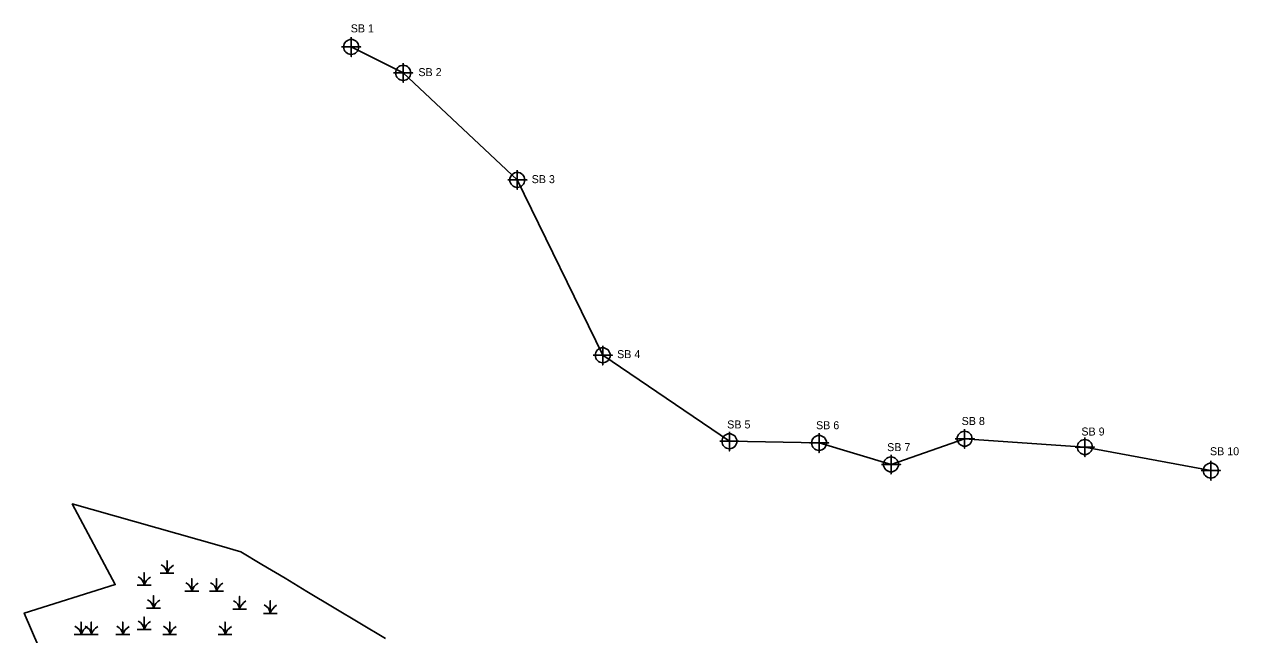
# Model space of a CAD drawing. Extents: x 2058476 to 2058911, y 688598 to 689103.
# Drawn here: x 2058475.6 to 2058854.9, y 688912 to 689102.8 of the extents above; entities that cross this region are included whole.
import ezdxf

# ---------------------------------------------------------------- set-up
doc = ezdxf.new("R2010")
doc.units = 0
for name, color, linetype in [('Exist Environmental Wetland Boundary', 7, 'Continuous'), ('Exist Hydro Jurisdictional Stream or Body of Water NEU Mitigable', 7, 'Continuous'), ('Exist Hydro Jurisdictional Stream or Body of Water NEU Mitigable Cogo Comment', 7, 'Continuous'), ('Exist Hydro Jurisdictional Stream or Body of Water NEU Mitigable Cogo Point CELL', 7, 'Continuous'), ('Exist Hydro Swamp or Marsh', 7, 'Continuous')]:
    doc.layers.add(name, color=color, linetype=linetype)

msp = doc.modelspace()

# ---------------------------------------------------------------- linework, layer by layer
at = {"layer": 'Exist Environmental Wetland Boundary'}
msp.add_lwpolyline([(2058588.45, 688910.87), (2058580.43, 688915.67), (2058572.43, 688920.46), (2058563.9, 688925.57), (2058557.1, 688929.64), (2058549.83, 688934), (2058543.26, 688937.93), (2058543.26, 688937.93), (2058536.49, 688939.85), (2058490.58, 688952.88), (2058504.01, 688927.66), (2058475.61, 688918.78), (2058492.26, 688880.08)], dxfattribs=at)
at = {"layer": 'Exist Hydro Jurisdictional Stream or Body of Water NEU Mitigable'}
msp.add_lwpolyline([(2058577.72, 689095.69), (2058593.95, 689087.58), (2058629.6, 689054.14), (2058656.28, 688999.33), (2058695.83, 688972.46), (2058723.84, 688971.95), (2058746.31, 688965.24), (2058769.31, 688973.26), (2058806.85, 688970.66), (2058846.21, 688963.3)], dxfattribs=at)
at = {"layer": 'Exist Hydro Jurisdictional Stream or Body of Water NEU Mitigable Cogo Point CELL'}
for points in [[(2058577.72, 689098.69), (2058577.72, 689092.69), (2058577.72, 689095.69), (2058580.72, 689095.69), (2058574.72, 689095.69)], [(2058593.95, 689090.58), (2058593.95, 689084.58), (2058593.95, 689087.58), (2058596.95, 689087.58), (2058590.95, 689087.58)], [(2058629.6, 689057.14), (2058629.6, 689051.14), (2058629.6, 689054.14), (2058632.6, 689054.14), (2058626.6, 689054.14)], [(2058656.28, 689002.33), (2058656.28, 688996.33), (2058656.28, 688999.33), (2058659.28, 688999.33), (2058653.28, 688999.33)], [(2058769.31, 688976.26), (2058769.31, 688970.26), (2058769.31, 688973.26), (2058772.31, 688973.26), (2058766.31, 688973.26)], [(2058695.83, 688975.46), (2058695.83, 688969.46), (2058695.83, 688972.46), (2058698.83, 688972.46), (2058692.83, 688972.46)], [(2058723.84, 688974.95), (2058723.84, 688968.95), (2058723.84, 688971.95), (2058726.84, 688971.95), (2058720.84, 688971.95)], [(2058806.85, 688973.66), (2058806.85, 688967.66), (2058806.85, 688970.66), (2058809.85, 688970.66), (2058803.85, 688970.66)], [(2058746.31, 688968.24), (2058746.31, 688962.24), (2058746.31, 688965.24), (2058749.31, 688965.24), (2058743.31, 688965.24)], [(2058846.21, 688966.3), (2058846.21, 688960.3), (2058846.21, 688963.3), (2058849.21, 688963.3), (2058843.21, 688963.3)]]:
    msp.add_lwpolyline(points, dxfattribs=at)
for centre in [(2058577.72, 689095.69), (2058593.95, 689087.58), (2058629.6, 689054.14), (2058656.28, 688999.33), (2058695.83, 688972.46), (2058723.84, 688971.95), (2058769.31, 688973.26), (2058806.85, 688970.66), (2058746.31, 688965.24), (2058846.21, 688963.3)]:
    msp.add_circle(centre, 2.34, dxfattribs=at)
at = {"layer": 'Exist Hydro Swamp or Marsh'}
msp.add_line((2058515.96, 688922.07), (2058515.96, 688922.07), dxfattribs=at)
for points in [[(2058518.07, 688931.21), (2058520.22, 688931.21), (2058520.22, 688935.15), (2058520.22, 688931.21), (2058522.37, 688931.21)], [(2058510.89, 688927.48), (2058513.04, 688927.48), (2058513.04, 688931.43), (2058513.04, 688927.48), (2058515.19, 688927.48)], [(2058525.79, 688925.62), (2058527.94, 688925.62), (2058527.94, 688929.56), (2058527.94, 688925.62), (2058530.09, 688925.62)], [(2058533.51, 688925.62), (2058535.66, 688925.62), (2058535.66, 688929.56), (2058535.66, 688925.62), (2058537.81, 688925.62)], [(2058513.81, 688920.29), (2058515.96, 688920.29), (2058515.96, 688924.24), (2058515.96, 688920.29), (2058518.12, 688920.29)], [(2058540.7, 688920.02), (2058542.85, 688920.02), (2058542.85, 688923.97), (2058542.85, 688920.02), (2058545, 688920.02)], [(2058550.28, 688918.69), (2058552.43, 688918.69), (2058552.43, 688922.64), (2058552.43, 688918.69), (2058554.58, 688918.69)], [(2058491.19, 688912.04), (2058493.34, 688912.04), (2058493.34, 688915.98), (2058493.34, 688912.04), (2058495.49, 688912.04)], [(2058494.38, 688912.04), (2058496.53, 688912.04), (2058496.53, 688915.98), (2058496.53, 688912.04), (2058498.69, 688912.04)], [(2058504.23, 688912.04), (2058506.38, 688912.04), (2058506.38, 688915.98), (2058506.38, 688912.04), (2058508.53, 688912.04)], [(2058510.89, 688913.63), (2058513.04, 688913.63), (2058513.04, 688917.58), (2058513.04, 688913.63), (2058515.19, 688913.63)], [(2058518.87, 688912.04), (2058521.02, 688912.04), (2058521.02, 688915.98), (2058521.02, 688912.04), (2058523.17, 688912.04)], [(2058536.17, 688912.04), (2058538.32, 688912.04), (2058538.32, 688915.98), (2058538.32, 688912.04), (2058540.47, 688912.04)]]:
    msp.add_lwpolyline(points, dxfattribs=at)
for centre, radius, start, end in [((2058517.16, 688930.99), 3.07, 4.1403, 67.535), ((2058524.78, 688929.69), 4.81, 122.1274, 161.6222), ((2058509.97, 688927.26), 3.07, 4.1403, 67.535), ((2058517.6, 688925.97), 4.81, 122.1274, 161.6222), ((2058524.88, 688925.39), 3.07, 4.1403, 67.535), ((2058532.5, 688924.1), 4.81, 122.1274, 161.6222), ((2058532.59, 688925.39), 3.07, 4.1403, 67.535), ((2058540.22, 688924.1), 4.81, 122.1274, 161.6222), ((2058512.9, 688920.07), 3.07, 4.1403, 67.535), ((2058520.53, 688918.78), 4.81, 122.1274, 161.6222), ((2058539.78, 688919.8), 3.07, 4.1403, 67.535), ((2058547.41, 688918.51), 4.81, 122.1274, 161.6222), ((2058549.36, 688918.47), 3.07, 4.1403, 67.535), ((2058556.99, 688917.18), 4.81, 122.1274, 161.6222), ((2058509.97, 688913.41), 3.07, 4.1403, 67.535), ((2058517.6, 688912.12), 4.81, 122.1274, 161.6222), ((2058490.27, 688911.81), 3.07, 4.1403, 67.535), ((2058497.9, 688910.52), 4.81, 122.1274, 161.6222), ((2058493.47, 688911.81), 3.07, 4.1403, 67.535), ((2058501.1, 688910.52), 4.81, 122.1274, 161.6222), ((2058503.32, 688911.81), 3.07, 4.1403, 67.535), ((2058510.94, 688910.52), 4.81, 122.1274, 161.6222), ((2058517.96, 688911.81), 3.07, 4.1403, 67.535), ((2058525.58, 688910.52), 4.81, 122.1274, 161.6222), ((2058535.26, 688911.81), 3.07, 4.1403, 67.535), ((2058542.88, 688910.52), 4.81, 122.1274, 161.6222)]:
    msp.add_arc(centre, radius, start, end, dxfattribs=at)

# ---------------------------------------------------------------- texts
at = {"layer": 'Exist Hydro Jurisdictional Stream or Body of Water NEU Mitigable Cogo Comment'}
for s, p in [('SB 1', (2058577.57, 689100.23)), ('SB 2', (2058598.7, 689086.56)), ('SB 3', (2058634.08, 689053.12)), ('SB 4', (2058660.77, 688998.43)), ('SB 8', (2058768.37, 688977.54)), ('SB 5', (2058695.15, 688976.47)), ('SB 6', (2058722.9, 688976.22)), ('SB 9', (2058805.77, 688974.26)), ('SB 7', (2058745.11, 688969.38)), ('SB 10', (2058845.93, 688968.1))]:
    msp.add_text(s, height=2.5, dxfattribs=at).set_placement(p)

doc.saveas('drawing.dxf')
